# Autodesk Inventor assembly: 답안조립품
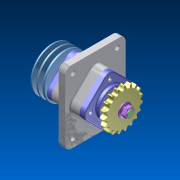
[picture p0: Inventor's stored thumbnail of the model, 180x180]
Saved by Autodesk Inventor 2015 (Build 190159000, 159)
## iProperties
Created: 2026-07
Part Number: 답안조립품
Document SubType Name: Assembly
Designer: user
Author: user
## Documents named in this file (12)
- C:\Users\user\Desktop\760705V1005\답안조립품.iam
- C:\Users\user\Desktop\760705V1005\본체.ipt
- C:\Users\user\Desktop\760705V1005\가져온 구성요소\6각 구멍붙이 볼트 M6x16\6각 구멍붙이 볼트 M6x16.ipt
- C:\Users\user\Desktop\760705V1005\가져온 구성요소\6각 플랜지 너트 M16\6각 플랜지 너트 M16.ipt
- C:\Users\user\Desktop\760705V1005\가져온 구성요소\V-벨트풀리\V-벨트풀리.ipt
- C:\Users\user\Desktop\760705V1005\가져온 구성요소\깊은 홈 볼 베어링 6206\깊은 홈 볼 베어링 6206.ipt
- C:\Users\user\Desktop\760705V1005\가져온 구성요소\오일 실 30 45 8\오일 실 30 45 8.ipt
- C:\Users\user\Desktop\760705V1005\가져온 구성요소\체인 스프로킷\체인 스프로킷.ipt
- C:\Users\user\Desktop\760705V1005\가져온 구성요소\축\축.ipt
- C:\Users\user\Desktop\760705V1005\가져온 구성요소\칼라\칼라.ipt
- C:\Users\user\Desktop\760705V1005\가져온 구성요소\커버\커버.ipt
- C:\Users\user\Desktop\760705V1005\가져온 구성요소\평행 키 6x6x20\평행 키 6x6x20.ipt
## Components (11 placed, 3 different names)
1. 6각 구멍붙이 볼트 M6x16:1
2. 6각 플랜지 너트 M16:1
3. V-벨트풀리:1
4. 6각 플랜지 너트 M16:2
5. 6각 구멍붙이 볼트 M6x16:2
6. 6각 구멍붙이 볼트 M6x16:3
7. 6각 구멍붙이 볼트 M6x16:4
8. 6각 구멍붙이 볼트 M6x16:5
9. 6각 구멍붙이 볼트 M6x16:6
10. 6각 구멍붙이 볼트 M6x16:7
11. 6각 구멍붙이 볼트 M6x16:8
